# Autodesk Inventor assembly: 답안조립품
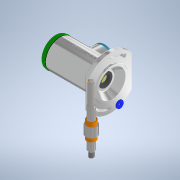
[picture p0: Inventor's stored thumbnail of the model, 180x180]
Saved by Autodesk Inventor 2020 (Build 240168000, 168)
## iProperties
Created: 2022-05
Part Number: 답안조립품
Document SubType Name: Assembly
Designer: Student
Author: Student
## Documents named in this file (16)
- C:\Users\Student\Desktop\720506V1022\답안조립품.iam
- C:\Users\Student\Desktop\720506V1022\본체.ipt
- C:\Users\Student\Desktop\720506V1022\베어링 6202.ipt
- C:\Users\Student\Desktop\720506V1022\탑 커버.ipt
- C:\Users\Student\Desktop\720506V1022\와셔 3 x 6.ipt
- C:\Users\Student\Desktop\720506V1022\십자볼트 M3 x 10.ipt
- C:\Users\Student\Desktop\720506V1022\사이드 커버.ipt
- 사이드 커버.ipt
- C:\Users\Student\Desktop\720506V1022\축.ipt
- C:\Users\Student\Desktop\720506V1022\멈춤링 35 x 1.6.ipt
- C:\Users\Student\Desktop\720506V1022\오일 실 15 x 30 x 7.ipt
- C:\Users\Student\Desktop\720506V1022\개스킷.ipt
- C:\Users\Student\Desktop\720506V1022\키 4 x 4.ipt
- C:\Users\Student\Desktop\720506V1022\부시1.ipt
- C:\Users\Student\Desktop\720506V1022\볼트 M4 x 10.ipt
- C:\Users\Student\Desktop\720506V1022\와셔 4 x 16.ipt
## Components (2 placed, 2 different names)
1. 개스킷:1
2. ISO 4017 M4 x 10:1
